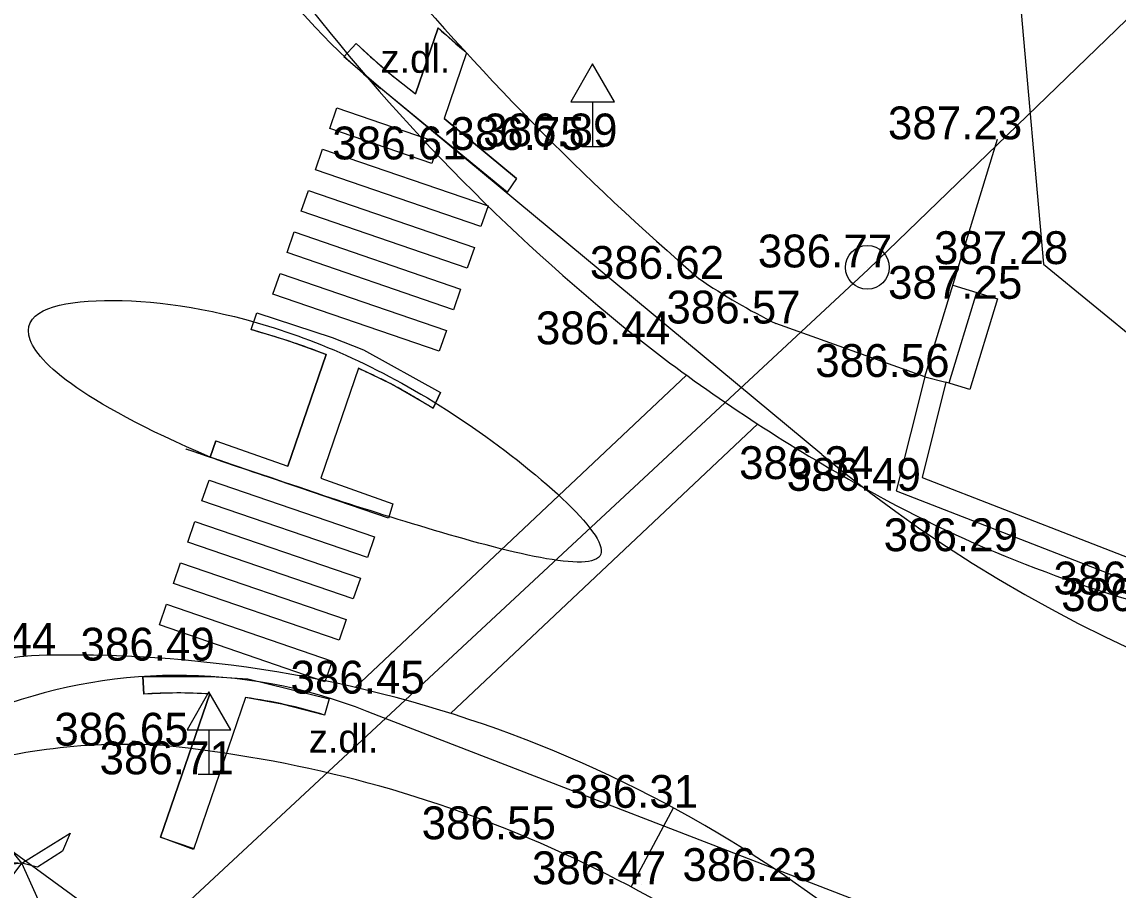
# Model space of a CAD drawing. Extents: x -438233 to -437334, y -1133133 to -1132623.
# Drawn here: x -438149.26 to -438124.22, y -1132952.39 to -1132932.56 of the extents above; entities that cross this region are included whole.
import ezdxf

# ---------------------------------------------------------------- set-up
doc = ezdxf.new("R2010")
doc.units = 0
for name, color, linetype in [('Vrstva 1', 7, 'Continuous'), ('Vrstva 10', 7, 'Continuous'), ('Vrstva 11', 7, 'Continuous'), ('Vrstva 15', 7, 'Continuous'), ('Vrstva 27', 7, 'Continuous'), ('Vrstva 3', 7, 'Continuous'), ('Vrstva 34', 7, 'Continuous'), ('Vrstva 40', 7, 'Continuous'), ('Vrstva 5', 7, 'Continuous'), ('Vrstva 55', 7, 'Continuous'), ('Vrstva 7', 7, 'Continuous')]:
    doc.layers.add(name, color=color, linetype=linetype)

msp = doc.modelspace()

# ---------------------------------------------------------------- linework, layer by layer
at = {"layer": 'Vrstva 1'}
for p, q in [((-438130.987, -1132942.441), (-438141.071, -1132934.08)), ((-438126.979, -1132935.245), (-438126.979, -1132935.245)), ((-438136.973, -1132935.488), (-438136.973, -1132935.488)), ((-438136.224, -1132935.407), (-438136.224, -1132935.407)), ((-438139.671, -1132935.704), (-438139.671, -1132935.704)), ((-438125.927, -1132938.095), (-438125.927, -1132938.095)), ((-438129.95, -1132938.171), (-438129.95, -1132938.171)), ((-438133.787, -1132938.432), (-438133.787, -1132938.432)), ((-438126.976, -1132938.888), (-438126.976, -1132938.888)), ((-438132.039, -1132939.452), (-438132.039, -1132939.452)), ((-438135.02, -1132939.927), (-438135.02, -1132939.927)), ((-438128.639, -1132940.673), (-438128.639, -1132940.673)), ((-438130.379, -1132943.006), (-438130.379, -1132943.006)), ((-438129.292, -1132943.274), (-438129.292, -1132943.274)), ((-438127.076, -1132944.653), (-438127.076, -1132944.653)), ((-438149.044, -1132947.04), (-438149.044, -1132947.04)), ((-438145.423, -1132947.152), (-438145.423, -1132947.152)), ((-438140.626, -1132947.906), (-438140.626, -1132947.906)), ((-438124.288, -1132954.91), (-438141.104, -1132948.421)), ((-438146.02, -1132949.095), (-438146.02, -1132949.095)), ((-438144.988, -1132949.749), (-438144.988, -1132949.749)), ((-438134.381, -1132950.515), (-438134.381, -1132950.515)), ((-438137.63, -1132951.233), (-438137.63, -1132951.233)), ((-438135.11, -1132952.26), (-438135.11, -1132952.26)), ((-438131.673, -1132952.187), (-438131.673, -1132952.187))]:
    msp.add_line(p, q, dxfattribs=at)
for points in [[(-438139.753, -1132932.7), (-438139.103, -1132933.269), (-438139.616, -1132934.766), (-438137.962, -1132936.138), (-438138.18, -1132936.454), (-438139.738, -1132935.172), (-438141.071, -1132934.08), (-438141.908, -1132933.364), (-438141.626, -1132933.057), (-438140.995, -1132933.635), (-438140.269, -1132934.203)], [(-438142.23, -1132934.996), (-438142.068, -1132934.524), (-438139.738, -1132935.323), (-438139.901, -1132935.796)], [(-438142.555, -1132935.942), (-438142.393, -1132935.469), (-438138.612, -1132936.767), (-438138.775, -1132937.24)], [(-438142.879, -1132936.888), (-438142.717, -1132936.415), (-438138.926, -1132937.716), (-438139.089, -1132938.189)], [(-438143.204, -1132937.834), (-438143.042, -1132937.361), (-438139.242, -1132938.665), (-438139.404, -1132939.138)], [(-438143.529, -1132938.78), (-438143.366, -1132938.307), (-438139.564, -1132939.612), (-438139.727, -1132940.085)], [(-438145.149, -1132943.501), (-438144.986, -1132943.028), (-438141.204, -1132944.326), (-438141.366, -1132944.799)], [(-438145.473, -1132944.446), (-438145.311, -1132943.973), (-438141.529, -1132945.271), (-438141.691, -1132945.744)], [(-438145.798, -1132945.392), (-438145.636, -1132944.919), (-438141.856, -1132946.217), (-438142.018, -1132946.689)], [(-438146.122, -1132946.338), (-438145.96, -1132945.865), (-438142.177, -1132947.163), (-438142.339, -1132947.636)]]:
    msp.add_lwpolyline(points, close=True, dxfattribs=at)
for centre, radius, start, end in [((-438130.547, -1132921.319), 16.541, 174.8014, 230.4908), ((-438110.563, -1132917.807), 32, 230.3365, 309.1186), ((-438145.706, -1132959.353), 11.861, 67.1677, 153.1295)]:
    msp.add_arc(centre, radius, start, end, dxfattribs=at)
msp.add_open_spline([(-438144.958, -1132942.509), (-438148, -1132941.199), (-438149.996, -1132939.359), (-438147.626, -1132938.737), (-438143.739, -1132939.25), (-438139.185, -1132941.338), (-438134.209, -1132945.715), (-438140.218, -1132944.135), (-438144.958, -1132942.509), (-438146.526, -1132941.975), (-438142.582, -1132943.306)], degree=3, dxfattribs=at)
at = {"layer": 'Vrstva 10'}
for p, q in [((-438134.081, -1132940.629), (-438141.651, -1132947.764)), ((-438132.454, -1132941.746), (-438139.469, -1132948.358))]:
    msp.add_line(p, q, dxfattribs=at)
for centre, radius, start, end in [((-438106.646, -1132904.004), 45.777, 217.6664, 231.6958), ((-438111.102, -1132908.912), 39.167, 232.3612, 240.5155), ((-438115.759, -1132917.821), 29.121, 239.8641, 255.5591), ((-438148.371, -1132954.689), 7.679, 95.0304, 157.0584), ((-438148.138, -1132975.891), 28.865, 47.3544, 91.7982)]:
    msp.add_arc(centre, radius, start, end, dxfattribs=at)
at = {"layer": 'Vrstva 11'}
for p, q in [((-438127.998, -1132938.576), (-438126.976, -1132938.888)), ((-438127.454, -1132938.742), (-438128.087, -1132940.815)), ((-438126.976, -1132938.888), (-438127.609, -1132940.961)), ((-438127.609, -1132940.961), (-438128.154, -1132940.795)), ((-438135.343, -1132952.323), (-438134.381, -1132950.515)), ((-438149.261, -1132951.783), (-438150.083, -1132950.774)), ((-438149.261, -1132951.783), (-438148.158, -1132951.093)), ((-438148.158, -1132951.093), (-438148.331, -1132951.502)), ((-438148.331, -1132951.502), (-438148.904, -1132951.872)), ((-438149.629, -1132951.752), (-438149.261, -1132951.783)), ((-438148.904, -1132951.872), (-438149.261, -1132951.783))]:
    msp.add_line(p, q, dxfattribs=at)
for points in [[(-438128.639, -1132940.673), (-438126.979, -1132935.245)], [(-438128.639, -1132940.673), (-438132.039, -1132939.452)], [(-438148.433, -1132953.625), (-438149.261, -1132951.783), (-438150.555, -1132951.934), (-438150.164, -1132952.144), (-438149.485, -1132952.076), (-438149.261, -1132951.783)]]:
    msp.add_lwpolyline(points, dxfattribs=at)
for centre, radius, start, end in [((-438092.402, -1132890.449), 63.365, 219.77595, 229.22236), ((-438125.547, -1132926.319), 14.65, 235.7747, 243.6961), ((-438146.915, -1132962.551), 13.486, 86.1956, 107.7042), ((-438148.846, -1132977.714), 28.758, 48.806, 84.3615)]:
    msp.add_arc(centre, radius, start, end, dxfattribs=at)
at = {"layer": 'Vrstva 15'}
for p, q in [((-438139.753, -1132932.7), (-438140.269, -1132934.203)), ((-438141.626, -1132933.057), (-438141.908, -1132933.364)), ((-438139.103, -1132933.269), (-438139.616, -1132934.766)), ((-438137.962, -1132936.138), (-438139.616, -1132934.766)), ((-438137.962, -1132936.138), (-438138.18, -1132936.454)), ((-438144.026, -1132939.587), (-438143.892, -1132939.205)), ((-438142.312, -1132940.16), (-438143.188, -1132942.714)), ((-438141.574, -1132940.473), (-438142.434, -1132942.982)), ((-438139.864, -1132941.388), (-438139.696, -1132941.026)), ((-438144.829, -1132942.13), (-438144.958, -1132942.509)), ((-438144.829, -1132942.13), (-438143.188, -1132942.714)), ((-438142.434, -1132942.982), (-438140.785, -1132943.569)), ((-438140.785, -1132943.569), (-438140.891, -1132943.898)), ((-438146.501, -1132947.514), (-438146.48, -1132947.918)), ((-438144.972, -1132947.915), (-438146.095, -1132951.188)), ((-438144.155, -1132947.997), (-438145.344, -1132951.464)), ((-438142.24, -1132948.023), (-438142.348, -1132948.395)), ((-438146.095, -1132951.188), (-438145.338, -1132951.447))]:
    msp.add_line(p, q, dxfattribs=at)
for points in [[(-438143.892, -1132939.205), (-438142.172, -1132939.775), (-438141.455, -1132940.057), (-438139.696, -1132941.026), (-438139.864, -1132941.388), (-438140.801, -1132940.849), (-438141.574, -1132940.473), (-438142.434, -1132942.982), (-438140.785, -1132943.569), (-438140.891, -1132943.898), (-438144.958, -1132942.509), (-438144.829, -1132942.13), (-438143.188, -1132942.714), (-438142.312, -1132940.16), (-438143.181, -1132939.847), (-438144.026, -1132939.587)], [(-438146.501, -1132947.514), (-438144.944, -1132947.514), (-438144.101, -1132947.568), (-438142.24, -1132948.023), (-438142.348, -1132948.395), (-438143.324, -1132948.144), (-438144.155, -1132947.997), (-438145.344, -1132951.464), (-438146.095, -1132951.188), (-438144.972, -1132947.915), (-438145.708, -1132947.89), (-438146.48, -1132947.918)]]:
    msp.add_lwpolyline(points, close=True, dxfattribs=at)
for centre, radius, start, end in [((-438128.804, -1132920.841), 16.141, 227.2863, 230.3548), ((-438130.547, -1132921.319), 16.141, 226.654, 232.9654), ((-438145.706, -1132959.353), 11.461, 86.3279, 93.8691), ((-438145.706, -1132959.353), 11.461, 72.9615, 82.2192)]:
    msp.add_arc(centre, radius, start, end, dxfattribs=at)
for points, degree in [([(-438144.026, -1132939.587), (-438143.967, -1132939.604), (-438143.393, -1132939.773), (-438142.832, -1132939.956), (-438142.312, -1132940.16)], 3), ([(-438141.574, -1132940.473), (-438141.039, -1132940.717), (-438140.478, -1132941.013), (-438139.864, -1132941.388)], 2)]:
    msp.add_open_spline(points, degree=degree, dxfattribs=at)
at = {"layer": 'Vrstva 27'}
msp.add_circle((-438129.95, -1132938.171), 0.5, dxfattribs=at)
at = {"layer": 'Vrstva 34'}
for p, q in [((-438136.224, -1132934.389), (-438136.224, -1132935.407)), ((-438136.474, -1132935.407), (-438135.974, -1132935.407)), ((-438144.988, -1132948.731), (-438144.988, -1132949.749)), ((-438145.238, -1132949.749), (-438144.738, -1132949.749))]:
    msp.add_line(p, q, dxfattribs=at)
for points in [[(-438136.724, -1132934.389), (-438135.724, -1132934.389), (-438136.224, -1132933.523)], [(-438145.488, -1132948.731), (-438144.488, -1132948.731), (-438144.988, -1132947.865)]]:
    msp.add_lwpolyline(points, close=True, dxfattribs=at)
at = {"layer": 'Vrstva 5'}
for p, q in [((-438126.705, -1132929.331), (-438125.927, -1132938.095)), ((-438125.927, -1132938.095), (-438115.881, -1132946.325))]:
    msp.add_line(p, q, dxfattribs=at)
at = {"layer": 'Vrstva 55'}
for points in [[(-438100.584, -1132911.605), (-438109.29, -1132918.26), (-438129.93, -1132938.22), (-438146.51, -1132953.64)], [(-438074.959, -1133013.61), (-438076.856, -1133009.846), (-438083.298, -1132998.719), (-438115.192, -1132972.054), (-438146.469, -1132953.711), (-438176.9, -1132931.48)]]:
    msp.add_lwpolyline(points, dxfattribs=at)
at = {"layer": 'Vrstva 7'}
for points in [[(-438128.639, -1132940.673), (-438129.292, -1132943.274), (-438123.197, -1132945.641), (-438117.845, -1132946.752), (-438117.048, -1132945.369)], [(-438128.154, -1132940.795), (-438128.7, -1132942.968), (-438123.055, -1132945.16), (-438118.098, -1132946.189), (-438117.44, -1132945.048)], [(-438128.639, -1132940.673), (-438128.154, -1132940.795)]]:
    msp.add_lwpolyline(points, dxfattribs=at)

# ---------------------------------------------------------------- texts
at = {"layer": 'Vrstva 3'}
for s, p in [('386.89 ', (-438138.724, -1132935.407)), ('387.23 ', (-438129.479, -1132935.245)), ('386.75 ', (-438139.473, -1132935.488)), ('386.61 ', (-438142.171, -1132935.704)), ('387.28 ', (-438128.427, -1132938.095)), ('386.77 ', (-438132.45, -1132938.171)), ('386.62 ', (-438136.287, -1132938.432)), ('387.25 ', (-438129.476, -1132938.888)), ('386.57 ', (-438134.539, -1132939.452)), ('386.44 ', (-438137.52, -1132939.927)), ('386.56 ', (-438131.139, -1132940.673)), ('386.34 ', (-438132.879, -1132943.006)), ('386.49 ', (-438131.792, -1132943.274)), ('386.29 ', (-438129.576, -1132944.653)), ('386.36 ', (-438125.697, -1132945.641)), ('386.24 ', (-438125.521, -1132946.022)), ('386.44 ', (-438151.544, -1132947.04)), ('386.49 ', (-438147.923, -1132947.152)), ('386.45 ', (-438143.126, -1132947.906)), ('386.65 ', (-438148.52, -1132949.095)), ('386.71 ', (-438147.488, -1132949.749)), ('386.31 ', (-438136.881, -1132950.515)), ('386.55 ', (-438140.13, -1132951.233)), ('386.47 ', (-438137.61, -1132952.26)), ('386.23 ', (-438134.173, -1132952.187))]:
    msp.add_text(s, height=0.75, dxfattribs=at).set_placement(p)
at = {"layer": 'Vrstva 40'}
for p in [(-438141.07, -1132933.725), (-438142.708, -1132949.252)]:
    msp.add_text('z.dl.', height=0.65, dxfattribs=at).set_placement(p)

doc.saveas('drawing.dxf')
